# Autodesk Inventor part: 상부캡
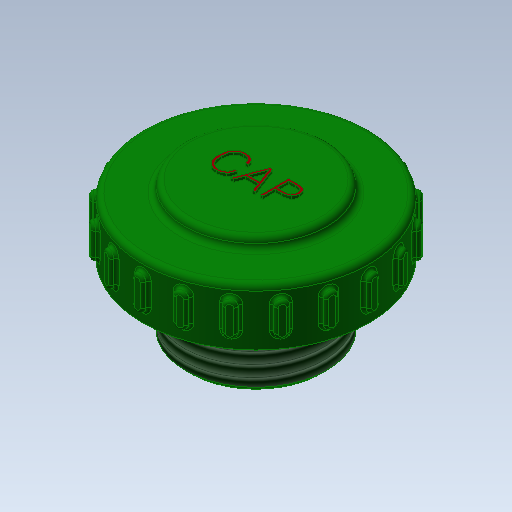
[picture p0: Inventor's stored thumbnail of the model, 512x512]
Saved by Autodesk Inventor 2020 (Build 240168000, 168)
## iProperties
Created: 2015-12
Part Number: 상부캡
Material: PC/ABS 플라스틱
Document SubType Name: Modeling
Designer: mduedu
Density: 7.86 g/cm^3
Appearance: 진녹색
Author: mduedu
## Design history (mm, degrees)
sketch "스케치1"
  geometry: C1 r 12.5 at (0, 0); C2 r 8 at (0, 0); 1 further point
  constraints: 2 centre point, 2 coincident
  dimensions: "d1" = 25 diameter of C1; "d3" = 16 diameter of C2
extrude "돌출1" new body sketch "스케치1" distance "d4" = 12; taper "d6" = 0 deg; dims "d5" = 12, "d7" = 0
sketch "스케치2"
  geometry: C1 r 20 at (0, 0); C2 r 12.5 at (0, 0) reference; 1 further point
  constraints: 1 centre point, 1 coincident
  dimensions: "d8" = 40 diameter of C1
extrude "돌출2" join sketch "스케치2" distance "d10" = 10; taper "d11" = 0 deg
extrude "돌출3" cut sketch "스케치1" extent not by distance; stored distance "d34" = 10; taper "d35" = 0 deg
sketch "스케치5"
  geometry: L1 (-20, 0)-(-20, 10) reference; L2 (-20, 10)-(-12.5, 10) reference; L3 (-12.5, 10)-(-12.5, 12) reference; L4 (-12.5, 12)-(12.5, 12) reference; L5 (12.5, 12)-(12.5, 10) reference; L6 (12.5, 10)-(20, 10) reference; L7 (20, 10)-(20, 0) reference; L8 (20, 0)-(12.5, 0) reference; L9 (12.5, 0)-(12.5, -12) reference; L10 (12.5, -12)-(8, -12) reference; L11 (8, -12)-(8, 0) reference; L12 (8, 0)-(-8, 0) reference; L13 (-8, 0)-(-8, -12) reference; L14 (-8, -12)-(-12.5, -12) reference; L15 (-12.5, -12)-(-12.5, 0) reference; L16 (-12.5, 0)-(-20, 0) reference; L17 (12.5, 0)-(10.5, 0); L18 (10.5, 0)-(10.5, -1); L19 (10.5, -1)-(12.5, -1); L20 (12.5, -1)-(12.5, 0); 2 further points
  constraints: 8 end point, 2 parallel, 1 horizontal, 1 midpoint, 1 perpendicular, 1 vertical alignment, 2 other
  dimensions: "d36" = 2 distance of L19.end L18.end; "d37" = 1 distance of L18.end L17.end
revolve "회전1" sketch "스케치5" stored, may be unused: angle "d38" = 90 deg
feature "스레드1" dims "d39" = 10, "d40" = 0
chamfer "모따기3" distance "d41" = 1; stored, may be unused: second distance "d42" = 2, angle "d43" = 45 deg
fillet "모깎기4" dims "d44" = 3
node "작업 평면1"
sketch "스케치7"
  geometry: L1 (1, 0)-(-1, 0); L2 (-1, 0)-(-1, 20.976); L3 (1, 20.976)-(1, 0); C1 r 20 at (0, 0) reference; A1 r 21 centre (0, 0) between (1, 20.976) and (-1, 20.976); 2 further points
  constraints: 6 end point, 2 coincident, 2 point on circle, 1 centre point, 1 horizontal, 1 midpoint, 1 parallel, 1 perpendicular
  dimensions: "d48" = 2 distance of L1.start L1.end; "d49" = 1 radial gap between concentric circles of A1 C1
extrude "돌출4" join sketch "스케치7" distance "d50" = 3; taper "d52" = 0 deg; dims "d51" = 3, "d53" = 0
fillet "모깎기5" dims "d54" = 1
fillet "모깎기6" dims "d55" = 0.5
fillet "모깎기7" dims "d59" = 1
sketch "스케치8"
  geometry: 2 further points
  constraints: 1 coincident, 1 other
feature "엠보싱1" sketch "스케치8" dims "d60" = 0.5, "d61" = 0
node "솔리드1"
pattern_circular "원형 패턴1" dims angle "d57" = 360 deg
node "절단 모서리 투영1"
node "절단 모서리 투영3"
